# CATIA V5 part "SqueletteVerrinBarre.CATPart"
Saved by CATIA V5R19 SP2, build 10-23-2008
Part number: SqueletteVerinBarre
Publications: "DroiteCG", "PointG", "PointC", "Plane.1", "BodyVerinBarre"
Bounding box of the stored display mesh (mm): x -54.98 to -10, y 11.213 to 91.213, z 156.233 to 186.194
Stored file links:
  D:\France\IFMA\IAO\Projet\SqueletteVerrinBarre.CATPart
  D:\France\IFMA\IAO\Projet\pruangdaja_CAO.CATProduct
  D:\France\IFMA\IAO\Projet\SquelettePrin.CATPart
  D:\France\IFMA\IAO\Projet\SqueletteBCD.CATPart
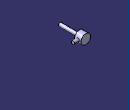
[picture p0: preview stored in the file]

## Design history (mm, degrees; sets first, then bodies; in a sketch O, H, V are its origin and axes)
External parameters (linked from other documents)
  External.Largeur = 10 mm
  External.RayonTrou = 5 mm
  External.RayonTrouBCD = 5 mm
Set1
  Point1: linked copy from another document
  Point2: linked copy from another document
  Plane1: linked copy from another document
Set2
  Line1: type PtPt, FirstPoint Point1, SecondPoint Point2
  Sketch1 on Plane1, origin (-40, 0, 0), H (0, 1, 0), V (0, 0, 1)
    line L1 (91.2132, 171.2132) -> (91.2132, 156.2132)
    line L2 (91.2132, 156.2132) -> (71.2132, 156.2132)
    line L3 (71.2132, 156.2132) -> (71.2132, 166.2132)
    line L4 (71.2132, 166.2132) -> (11.2132, 166.2132)
    line L5 (11.2132, 166.2132) -> (11.2132, 171.2132)
    line L6 (11.2132, 171.2132) -> (91.2132, 171.2132)
    reference projected point E1 (11.2132, 171.2132) from Point2
    reference projected line E2 (81.2132, 171.2132) -> (11.2132, 171.2132) from Line1
    reference projected point E3 (81.2132, 171.2132) from Point1
    reference projected point E4 (81.2132, 171.2132) from Point1
    distance L1 E3 = 10
    distance L3 E4 = 10
    distance L4 L6 = 5 {= External.RayonTrou}
    distance L2 L6 = 15
    vertical: L1 V, L3 V, L5 V
    horizontal: L2 H, L4 H, L6 H
    coincidence: L5 E1, L6 E2
Body1 (main body)
  Shaft1: profile Sketch1, axis Sketch1.L6, angle 360
  Sketch2 on Plane1, origin (-40, 0, 0), H (0, 1, 0), V (0, 0, 1)
    circle A1 centre (81.2132, 171.2132) radius 5
    point P1 (81.2132, 171.2132)
    reference projected point E1 (81.2132, 171.2132) from Point1
    radius A1 = 5 {= External.RayonTrouBCD}
    coincidence: P1 E1
  Pad1: profile Sketch2, direction (1, 0, 0), length 30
